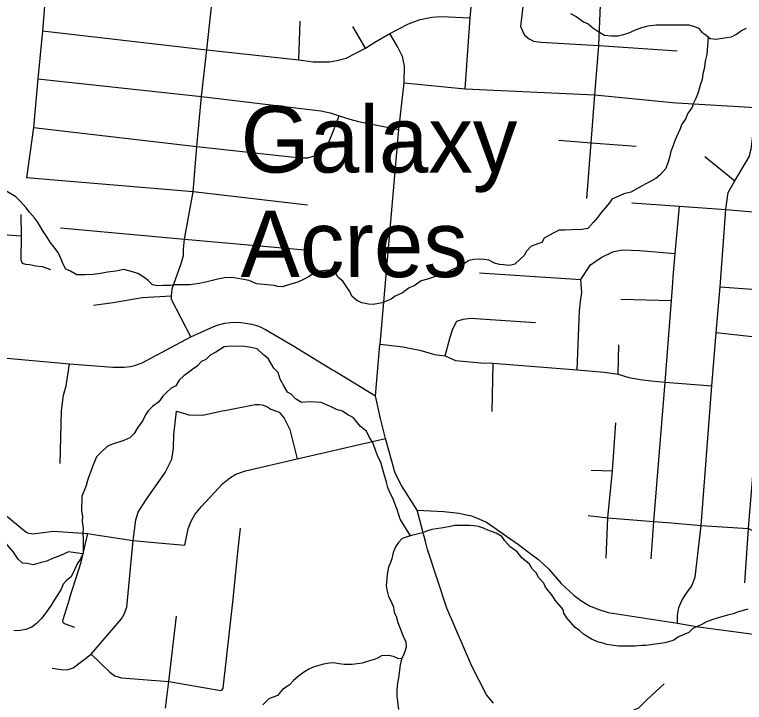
# Model space of a CAD drawing. Extents: x 0 to 34, y 0 to 22.
# Drawn here: x 4.554 to 5.421, y 16.285 to 17.102 of the extents above; entities that cross this region are included whole.
import ezdxf

# ---------------------------------------------------------------- set-up
doc = ezdxf.new("R2010")
doc.units = 0
for name, color, linetype in [('GM_X_County_Road', 7, 'Continuous'), ('GM_X_Minor_River', 7, 'Continuous'), ('GM_X_Township_Subdivision', 7, 'Continuous'), ('GM_X_Unincorporated_Text', 7, 'Continuous')]:
    doc.layers.add(name, color=color, linetype=linetype)

msp = doc.modelspace()

# ---------------------------------------------------------------- linework, layer by layer
at = {"layer": 'GM_X_County_Road'}
for points in [[(4.98809, 16.70952), (4.98815, 16.71012), (5.01058, 16.96502), (5.01675, 17.02076), (5.08927, 17.01363), (5.09515, 17.09796), (5.11236, 17.27796)], [(5.08927, 17.01363), (5.24337, 17.00629), (5.33573, 16.9972)], [(5.33573, 16.9972), (5.34088, 16.9967), (5.4342, 16.99118), (5.44574, 16.99168), (5.45778, 16.99319), (5.47383, 16.99921), (5.48558, 17.00366)], [(4.5229, 16.69542), (4.6194, 16.68687), (4.67069, 16.68292), (4.67645, 16.68276), (4.68435, 16.68276), (4.69158, 16.68358), (4.69815, 16.68539), (4.70555, 16.68819), (4.76358, 16.71876), (4.78792, 16.7301), (4.79466, 16.73257), (4.8037, 16.73504), (4.81044, 16.73586), (4.81734, 16.73636), (4.82327, 16.73603), (4.8282, 16.73521), (4.83576, 16.73389), (4.84414, 16.73142), (4.8522, 16.72748), (4.88475, 16.70857), (4.93159, 16.6799)], [(4.98273, 16.64889), (4.98809, 16.70952)], [(4.93159, 16.6799), (4.93391, 16.67848), (4.98273, 16.64889)], [(5.03222, 16.51309), (5.01381, 16.5422), (5.00625, 16.55682), (4.99457, 16.59809), (4.98866, 16.62209), (4.98273, 16.64889)], [(5.04216, 16.47567), (5.03222, 16.51309)], [(5.03222, 16.51309), (5.06379, 16.51128), (5.08203, 16.50931), (5.09237, 16.50719)], [(5.09237, 16.50719), (5.09568, 16.50652), (5.10341, 16.50372), (5.11443, 16.49863), (5.13842, 16.48218), (5.15273, 16.47216), (5.16457, 16.46311), (5.17673, 16.45407), (5.18882, 16.4429), (5.2032, 16.42612), (5.21866, 16.41182), (5.22671, 16.40574), (5.2369, 16.39949), (5.24792, 16.39505), (5.25926, 16.3916), (5.3413, 16.37894), (5.36662, 16.37466), (5.40213, 16.36974), (5.42309, 16.36686), (5.44274, 16.36431), (5.44492, 16.36412)], [(5.12307, 16.28389), (5.11471, 16.29382), (5.09721, 16.32776), (5.06762, 16.39671), (5.04464, 16.46635), (5.04216, 16.47567)]]:
    msp.add_lwpolyline(points, dxfattribs=at)
at = {"layer": 'GM_X_Minor_River'}
for points in [[(5.21444, 17.10287), (5.22119, 17.09925), (5.22976, 17.09292), (5.2354, 17.09048), (5.24097, 17.08575), (5.24807, 17.08098), (5.25482, 17.07737), (5.26278, 17.07639), (5.27115, 17.07654), (5.27727, 17.07789), (5.28302, 17.07963), (5.29149, 17.08359), (5.29917, 17.08642), (5.30683, 17.08811), (5.31599, 17.08937), (5.32474, 17.08951), (5.33387, 17.08964), (5.34223, 17.08941), (5.34946, 17.08959), (5.35478, 17.08944), (5.36157, 17.08734), (5.36646, 17.08569), (5.37051, 17.08062), (5.37499, 17.07745), (5.3802, 17.07312), (5.3874, 17.07254), (5.39963, 17.07448), (5.40573, 17.07507), (5.41152, 17.07834), (5.41734, 17.08275), (5.42351, 17.08562)], [(5.37806, 17.0749), (5.37626, 17.05419), (5.37452, 17.04624), (5.37313, 17.03714), (5.37145, 17.03109), (5.37089, 17.02463), (5.36843, 17.01785), (5.36591, 17.00916), (5.36303, 17.00124), (5.36062, 16.99636), (5.35898, 16.99184), (5.35343, 16.98361), (5.35138, 16.97834), (5.34624, 16.97087), (5.34458, 16.96596), (5.34015, 16.95656), (5.33809, 16.95091), (5.33644, 16.94601), (5.33358, 16.93885), (5.33187, 16.93204), (5.33059, 16.92675), (5.32771, 16.91883), (5.32105, 16.9114), (5.3156, 16.90698), (5.31058, 16.90407), (5.30402, 16.90045), (5.29939, 16.89829), (5.28588, 16.89067), (5.27784, 16.88861), (5.26898, 16.88467), (5.2636, 16.88254), (5.26082, 16.87804), (5.25139, 16.86688), (5.24704, 16.86091), (5.24117, 16.8546), (5.23489, 16.84754), (5.22801, 16.84621), (5.21584, 16.84617), (5.20708, 16.84565), (5.20099, 16.84544), (5.19367, 16.84221), (5.18324, 16.83603), (5.18043, 16.83078), (5.16777, 16.82656), (5.16229, 16.82062), (5.15948, 16.81537), (5.15443, 16.81132), (5.14817, 16.80502), (5.14205, 16.80367), (5.13484, 16.80425), (5.12991, 16.80477), (5.12425, 16.80645), (5.11751, 16.81006), (5.11182, 16.8106), (5.10689, 16.81112), (5.09966, 16.81094), (5.09353, 16.80959), (5.08384, 16.80262), (5.07578, 16.7998), (5.06883, 16.79619), (5.06269, 16.79407), (5.05576, 16.79084), (5.0504, 16.78947), (5.04463, 16.78734), (5.03697, 16.78527), (5.02883, 16.77941), (5.02269, 16.77729), (5.01491, 16.77103), (5.00606, 16.76709), (5.0014, 16.7638), (4.99563, 16.76129), (4.99063, 16.75915), (4.97993, 16.75716), (4.97462, 16.75769), (4.96668, 16.75943), (4.96066, 16.76188), (4.95472, 16.76738), (4.95221, 16.77278), (4.94854, 16.77784), (4.9438, 16.7852), (4.9386, 16.78954), (4.93533, 16.79534), (4.92856, 16.79819), (4.92322, 16.79758), (4.91674, 16.797), (4.90944, 16.79416), (4.90324, 16.79014), (4.89707, 16.78689), (4.8913, 16.78438), (4.88516, 16.78227), (4.87826, 16.78018), (4.8725, 16.77843), (4.8668, 16.77859), (4.86228, 16.77986), (4.85392, 16.78048), (4.84596, 16.78146), (4.84142, 16.78197), (4.83277, 16.78563), (4.82596, 16.78697), (4.81726, 16.78873), (4.81081, 16.7893)], [(4.81081, 16.7893), (4.80358, 16.78912), (4.79555, 16.78744), (4.78445, 16.7847), (4.77374, 16.78233), (4.76228, 16.78075), (4.75619, 16.78054), (4.75163, 16.78066), (4.74402, 16.7805), (4.73944, 16.77986), (4.73069, 16.77973), (4.72384, 16.77954), (4.71779, 16.78085), (4.71261, 16.78594), (4.70777, 16.78988), (4.70066, 16.79427), (4.69424, 16.79597), (4.68368, 16.79894), (4.67449, 16.79691), (4.66457, 16.79566), (4.65616, 16.79399), (4.64739, 16.79309), (4.63787, 16.7926), (4.63292, 16.79236), (4.62798, 16.79249), (4.62049, 16.79689), (4.61485, 16.79933), (4.61123, 16.80591), (4.60984, 16.81052), (4.60588, 16.81901), (4.60074, 16.82562), (4.59633, 16.83146), (4.59196, 16.83844), (4.58829, 16.84349), (4.58504, 16.84967), (4.58139, 16.85548), (4.57772, 16.86016), (4.57181, 16.8668), (4.56778, 16.87224), (4.56113, 16.87966), (4.55558, 16.88515), (4.5436, 16.89234)], [(5.0243, 16.48247), (5.01218, 16.50226), (5.01042, 16.50764), (5.00869, 16.51378), (5.0062, 16.51995), (5.00335, 16.52726), (5.00009, 16.53306), (4.99723, 16.54), (4.99588, 16.54613), (4.99274, 16.55688), (4.9893, 16.56992), (4.98568, 16.57688), (4.98319, 16.58304), (4.97967, 16.59342), (4.97564, 16.59924), (4.97205, 16.60696), (4.96497, 16.61249), (4.95613, 16.62302), (4.94975, 16.62624), (4.94341, 16.63061), (4.93662, 16.6327), (4.93024, 16.63593), (4.91821, 16.64083), (4.91138, 16.6414), (4.90302, 16.64164), (4.89501, 16.64072), (4.8879, 16.6451), (4.88274, 16.65096), (4.87824, 16.65337), (4.87387, 16.66073), (4.86952, 16.66846), (4.86708, 16.67653), (4.86189, 16.68162), (4.85935, 16.68626), (4.85536, 16.69323), (4.84977, 16.69758), (4.84236, 16.70464), (4.8348, 16.70637), (4.82722, 16.70734), (4.81164, 16.70778), (4.80287, 16.70688), (4.7932, 16.70068), (4.78625, 16.69706), (4.78117, 16.69187), (4.77617, 16.68973), (4.77107, 16.68416), (4.76565, 16.6805), (4.76098, 16.67682), (4.75516, 16.67242), (4.7497, 16.66724), (4.74572, 16.66087), (4.73994, 16.65799), (4.73486, 16.65318), (4.73017, 16.64836), (4.72542, 16.64164), (4.71805, 16.63613), (4.71258, 16.63095), (4.70941, 16.62609), (4.70657, 16.6197), (4.70025, 16.61073), (4.69626, 16.60399), (4.69079, 16.59881), (4.68386, 16.59558), (4.66929, 16.59104), (4.6639, 16.58852), (4.65687, 16.58186), (4.65139, 16.5763), (4.64734, 16.5669), (4.64525, 16.5601), (4.64239, 16.55294), (4.64075, 16.54842), (4.63906, 16.54237), (4.63621, 16.53522), (4.63415, 16.52956), (4.63369, 16.51244), (4.63464, 16.50556), (4.63448, 16.49947), (4.63539, 16.49107), (4.63525, 16.48574), (4.63542, 16.47812), (4.63563, 16.47164), (4.63537, 16.46213), (4.63212, 16.4546), (4.62856, 16.44937), (4.62532, 16.44223), (4.62129, 16.43396), (4.61624, 16.42991), (4.61192, 16.42508), (4.60948, 16.41906), (4.6055, 16.41269), (4.60114, 16.40596), (4.59756, 16.40035), (4.59122, 16.39101), (4.5861, 16.38429), (4.58023, 16.37837), (4.57441, 16.37396), (4.5675, 16.37148), (4.55833, 16.36984), (4.55301, 16.36999)], [(4.63495, 16.46116), (4.61829, 16.46337), (4.60866, 16.45907), (4.59906, 16.45552), (4.59252, 16.45266), (4.58448, 16.4506), (4.57604, 16.44817), (4.56923, 16.4495), (4.56354, 16.45004), (4.55835, 16.45476), (4.55288, 16.46329), (4.54624, 16.47109), (4.5422, 16.47615), (4.53667, 16.48278), (4.53263, 16.48784), (4.52933, 16.49251), (4.52263, 16.49802), (4.50969, 16.50217)], [(5.18454, 16.42168), (5.18277, 16.4263), (5.17648, 16.43295), (5.17397, 16.43835), (5.16878, 16.44344), (5.16551, 16.44887), (5.15658, 16.45635), (5.15108, 16.46374), (5.14288, 16.46968), (5.13622, 16.47672), (5.13294, 16.48176), (5.1262, 16.48576), (5.11603, 16.48947), (5.11114, 16.49151), (5.10511, 16.49358), (5.09981, 16.49449), (5.09451, 16.49502), (5.08728, 16.49484), (5.08234, 16.49498), (5.07701, 16.49474), (5.07128, 16.49376), (5.06324, 16.49208), (5.05484, 16.49079), (5.0495, 16.49018), (5.04336, 16.48807), (5.03875, 16.48629), (5.03071, 16.48423), (5.02572, 16.48284), (5.01921, 16.48112), (5.0146, 16.47935), (5.00991, 16.47453), (5.00635, 16.46968), (5.00389, 16.46289), (5.00216, 16.45532), (5.00051, 16.4508), (4.99808, 16.44515), (4.99717, 16.43947), (4.99621, 16.43226), (4.99558, 16.42314), (4.99655, 16.41664), (4.99828, 16.4105), (5.00155, 16.40469), (5.00402, 16.39777), (5.00499, 16.39165), (5.00715, 16.38702), (5.00924, 16.37973), (5.01564, 16.36355), (5.01888, 16.35661), (5.0191, 16.35089), (5.01784, 16.34636), (5.01657, 16.34182), (5.01376, 16.33619), (5.01205, 16.32938), (5.01105, 16.32027), (5.0101, 16.31344), (5.00881, 16.30815), (5.0082, 16.29941), (5.008, 16.29218), (5.01023, 16.27612)], [(5.42494, 16.39556), (5.41267, 16.39172), (5.40767, 16.38995), (5.40078, 16.38824), (5.38852, 16.38477), (5.38353, 16.38301), (5.37585, 16.38056), (5.36967, 16.37692), (5.35967, 16.37263), (5.35497, 16.36781), (5.34266, 16.36244), (5.33723, 16.35878), (5.32956, 16.35633), (5.3242, 16.35496), (5.31504, 16.35369), (5.30932, 16.35309), (5.30398, 16.35248), (5.29865, 16.35224), (5.29103, 16.35169), (5.28418, 16.3515), (5.27657, 16.35133), (5.27163, 16.35147), (5.26557, 16.3524), (5.25761, 16.35338), (5.25309, 16.35503), (5.2478, 16.35632), (5.23915, 16.35999), (5.2298, 16.36558), (5.22498, 16.37029), (5.21975, 16.37386), (5.20981, 16.38556), (5.20652, 16.3906), (5.2055, 16.3952), (5.19629, 16.40612), (5.19301, 16.41116), (5.18454, 16.42168)], [(5.01396, 16.33659), (5.00921, 16.3367), (5.00433, 16.33912), (4.99828, 16.34043), (4.9899, 16.3399), (4.9845, 16.337), (4.97989, 16.33523), (4.97183, 16.33279), (4.96685, 16.3314), (4.95502, 16.32983), (4.94551, 16.32971), (4.93945, 16.33064), (4.93301, 16.33159), (4.92806, 16.33134), (4.92118, 16.33001), (4.91544, 16.32865), (4.91007, 16.32689), (4.90431, 16.32477), (4.8985, 16.32112), (4.89114, 16.316), (4.88529, 16.31083), (4.8802, 16.30526), (4.87246, 16.30014), (4.86618, 16.29308), (4.85617, 16.28879), (4.84914, 16.28175)]]:
    msp.add_lwpolyline(points, dxfattribs=at)
at = {"layer": 'GM_X_Township_Subdivision'}
for points in [[(5.2336, 16.88318), (5.23886, 16.94949), (5.24337, 17.00629), (5.24801, 17.06473), (5.24996, 17.11306), (5.25136, 17.12144), (5.25535, 17.13142), (5.2753, 17.16534), (5.30483, 17.21722)], [(4.59116, 17.13115), (4.58739, 17.08214), (4.58173, 17.02521), (4.57646, 16.96752), (4.5683, 16.90769)], [(5.1581, 17.11458), (5.15485, 17.0876), (5.15982, 17.07727), (5.16514, 17.0729), (5.17054, 17.07016), (5.17932, 17.06876), (5.24801, 17.06473), (5.34095, 17.05858)], [(4.76358, 16.71876), (4.74063, 16.76321), (4.74033, 16.76765), (4.74107, 16.77578), (4.75204, 16.80587), (4.75456, 16.81531), (4.75475, 16.82291), (4.75594, 16.83508), (4.76629, 16.89117), (4.77063, 16.94509), (4.77628, 17.00418), (4.7825, 17.05961), (4.78797, 17.1107)], [(4.58739, 17.08214), (4.7825, 17.05961), (4.89175, 17.04782), (4.90872, 17.04538), (4.92813, 17.04538), (4.93699, 17.04698), (4.94793, 17.0499), (4.97074, 17.06159), (4.98206, 17.06886), (4.9997, 17.07897), (5.02211, 17.09062), (5.03599, 17.09596), (5.04961, 17.09862), (5.06076, 17.0995), (5.09515, 17.09796)], [(4.89175, 17.04782), (4.89322, 17.09371)], [(4.97074, 17.06159), (4.95575, 17.0876)], [(5.01675, 17.02076), (5.01705, 17.04057), (5.01492, 17.05172), (5.00891, 17.06376), (4.9997, 17.07897)], [(4.58173, 17.02521), (4.77628, 17.00418), (4.91786, 16.98741), (4.92879, 16.98477), (4.93954, 16.98137), (4.95236, 16.9776), (4.96254, 16.97478), (5.01058, 16.96502)], [(5.3413, 16.37894), (5.34163, 16.38798), (5.34295, 16.39752), (5.34689, 16.4064), (5.35281, 16.41577), (5.35825, 16.4223), (5.36231, 16.43329), (5.36946, 16.49489), (5.38216, 16.66076), (5.38756, 16.7235), (5.39207, 16.7781), (5.39883, 16.87016), (5.40181, 16.89013), (5.4096, 16.90411), (5.42641, 16.93278), (5.42906, 16.94163), (5.43137, 16.96075), (5.4342, 16.99118)], [(4.57646, 16.96752), (4.77063, 16.94509), (4.89316, 16.93142), (4.9024, 16.9316), (4.91164, 16.93424), (4.92013, 16.94148), (4.92766, 16.95102), (4.93238, 16.9629), (4.93954, 16.98137)], [(5.20039, 16.95252), (5.23886, 16.94949), (5.29223, 16.94545)], [(5.37384, 16.93296), (5.4096, 16.90411)], [(4.90215, 16.87508), (4.76629, 16.89117), (4.5683, 16.90769)], [(5.28716, 16.87821), (5.34366, 16.87393), (5.39883, 16.87016), (5.45446, 16.86522), (5.48021, 16.86333)], [(5.33638, 16.79021), (5.33862, 16.81775), (5.34366, 16.87393)], [(4.56151, 16.86418), (4.56211, 16.83865), (4.56136, 16.81039), (4.56299, 16.80655), (4.56714, 16.80537), (4.57216, 16.80492), (4.57941, 16.8033), (4.58695, 16.80241), (4.59657, 16.79886)], [(5.39207, 16.7781), (5.43543, 16.77527), (5.44446, 16.77438), (5.44836, 16.7773), (5.45446, 16.86522)], [(4.56211, 16.83865), (4.43076, 16.84811), (4.33929, 16.85497)], [(4.60854, 16.84819), (4.75594, 16.83508), (4.89892, 16.82236)], [(5.22643, 16.76078), (5.22776, 16.77165), (5.22677, 16.78695), (5.2381, 16.8043), (5.25084, 16.81314), (5.26465, 16.81987), (5.26792, 16.82058)], [(5.26792, 16.82058), (5.27597, 16.82235), (5.29615, 16.82128), (5.33862, 16.81775)], [(5.10642, 16.79509), (5.22677, 16.78695)], [(5.31011, 16.45509), (5.31318, 16.49968), (5.32677, 16.66518), (5.33438, 16.76217), (5.3358, 16.78306), (5.33638, 16.79021)], [(4.64775, 16.75641), (4.67126, 16.75981), (4.70558, 16.76558), (4.74033, 16.76765)], [(5.22217, 16.6797), (5.22509, 16.74976), (5.22643, 16.76078)], [(5.27421, 16.76359), (5.33438, 16.76217)], [(5.06536, 16.69633), (5.07138, 16.71863), (5.07457, 16.72855), (5.07952, 16.73739), (5.08696, 16.73987), (5.09545, 16.74094), (5.17297, 16.73598)], [(5.42134, 16.42689), (5.42563, 16.49126), (5.44393, 16.71306), (5.44039, 16.7166), (5.43357, 16.71837), (5.38756, 16.7235)], [(4.98815, 16.71012), (5.01545, 16.70695), (5.02501, 16.70518), (5.03528, 16.70306), (5.05297, 16.69775), (5.06536, 16.69633), (5.07775, 16.69067), (5.10784, 16.68819), (5.122, 16.68748), (5.22217, 16.6797), (5.25438, 16.67687), (5.27102, 16.67439), (5.28376, 16.6705), (5.29721, 16.66837), (5.31031, 16.6666), (5.32677, 16.66518), (5.38216, 16.66076)], [(5.27102, 16.67439), (5.27173, 16.70941)], [(4.5229, 16.69542), (4.50929, 16.53767), (4.50998, 16.53461), (4.51401, 16.53143), (4.56536, 16.48879), (4.56947, 16.48603), (4.57589, 16.4851), (4.6004, 16.48797), (4.64111, 16.48524), (4.65046, 16.48382)], [(4.60835, 16.56863), (4.60991, 16.63088), (4.61227, 16.64944), (4.61522, 16.66076), (4.6194, 16.68687)], [(5.122, 16.68748), (5.121, 16.63034)], [(4.80397, 16.63155), (4.83966, 16.63847), (4.84482, 16.63861), (4.8482, 16.63799), (4.85359, 16.63598), (4.85861, 16.6331), (4.86839, 16.62936), (4.87435, 16.62248), (4.88092, 16.60903), (4.88965, 16.57381)], [(4.74206, 16.58094), (4.74301, 16.58654), (4.74312, 16.60292), (4.74641, 16.63049)], [(4.74641, 16.63049), (4.76099, 16.62639), (4.77763, 16.62577), (4.80061, 16.6309), (4.80397, 16.63155)], [(5.25664, 16.45604), (5.25889, 16.5039), (5.26412, 16.55983), (5.26827, 16.6168)], [(4.75626, 16.47134), (4.76044, 16.49078), (4.76331, 16.49906), (4.76809, 16.50806), (4.77629, 16.51735), (4.80134, 16.54476), (4.80945, 16.55112), (4.81674, 16.55595), (4.82845, 16.55985), (4.88965, 16.57381), (4.99457, 16.59809)], [(4.59855, 16.32553), (4.6119, 16.32328), (4.61765, 16.32389), (4.62349, 16.3259), (4.64496, 16.34196), (4.68111, 16.38411), (4.68428, 16.38935), (4.68754, 16.39801), (4.69503, 16.47705), (4.69815, 16.50173), (4.70102, 16.51056), (4.70985, 16.52473), (4.73306, 16.55759), (4.74084, 16.57369), (4.74206, 16.58094)], [(5.23883, 16.5606), (5.26412, 16.55983)], [(5.23533, 16.50672), (5.25889, 16.5039), (5.31318, 16.49968), (5.31861, 16.4992)], [(5.31861, 16.4992), (5.33429, 16.49781), (5.36946, 16.49489), (5.42563, 16.49126), (5.45133, 16.47875)], [(4.64496, 16.34196), (4.66734, 16.3206), (4.67309, 16.31609), (4.6811, 16.31382), (4.73723, 16.30953), (4.79888, 16.29876), (4.80079, 16.29946), (4.80199, 16.30172), (4.81375, 16.4074), (4.81941, 16.46305), (4.82231, 16.49152)], [(4.61966, 16.40867), (4.61982, 16.40917), (4.6331, 16.4514), (4.64111, 16.48524)], [(4.65046, 16.48382), (4.69503, 16.47705), (4.72012, 16.47483), (4.75626, 16.47134)], [(4.62546, 16.37372), (4.61325, 16.37801), (4.61219, 16.37884), (4.61163, 16.38014), (4.61151, 16.38177), (4.61166, 16.38318), (4.61966, 16.40867)], [(4.73347, 16.27797), (4.73723, 16.30953), (4.74646, 16.38705)], [(5.29556, 16.057), (5.30138, 16.12428), (5.2767, 16.21349), (5.26067, 16.26464), (5.26206, 16.26842), (5.26583, 16.27001), (5.28507, 16.27377), (5.29544, 16.27845), (5.30554, 16.28807), (5.32575, 16.30695)]]:
    msp.add_lwpolyline(points, dxfattribs=at)

# ---------------------------------------------------------------- texts
at = {"layer": 'GM_X_Unincorporated_Text'}
for s, p in [('Galaxy', (4.82253, 16.91402)), ('Acres', (4.82253, 16.78985))]:
    msp.add_text(s, height=0.078977, rotation=0.00001, dxfattribs=at).set_placement(p)

doc.saveas('drawing.dxf')
